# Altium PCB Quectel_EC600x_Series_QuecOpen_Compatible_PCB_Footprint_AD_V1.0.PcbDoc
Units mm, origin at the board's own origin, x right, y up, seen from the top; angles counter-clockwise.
Board outline 152.4 x 101.6 mm, 2 copper layers (Top Layer, Bottom Layer); 1 components, 0 nets, 148 pads, 0 vias.
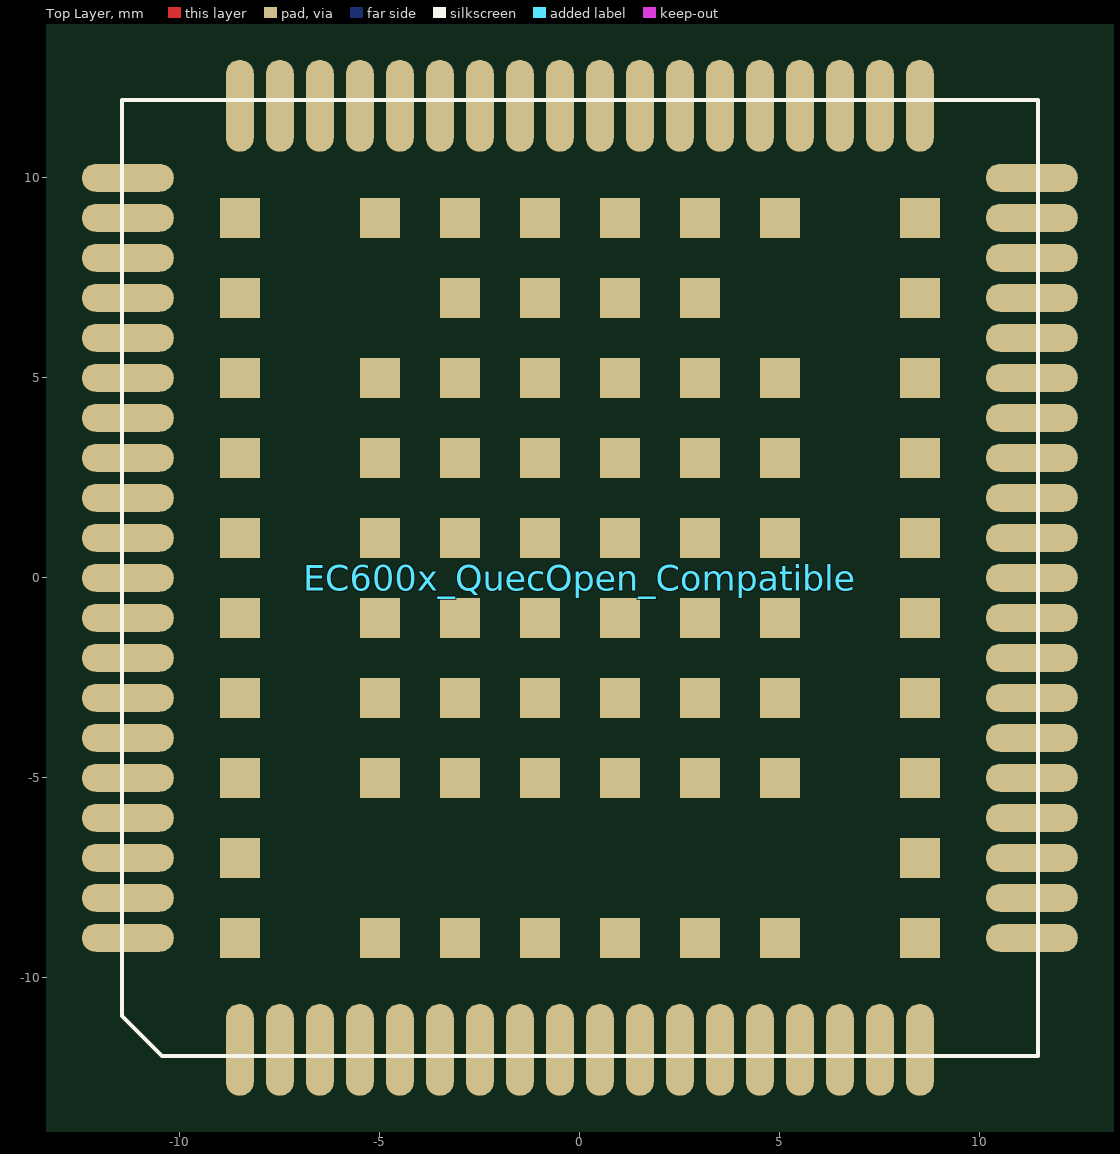
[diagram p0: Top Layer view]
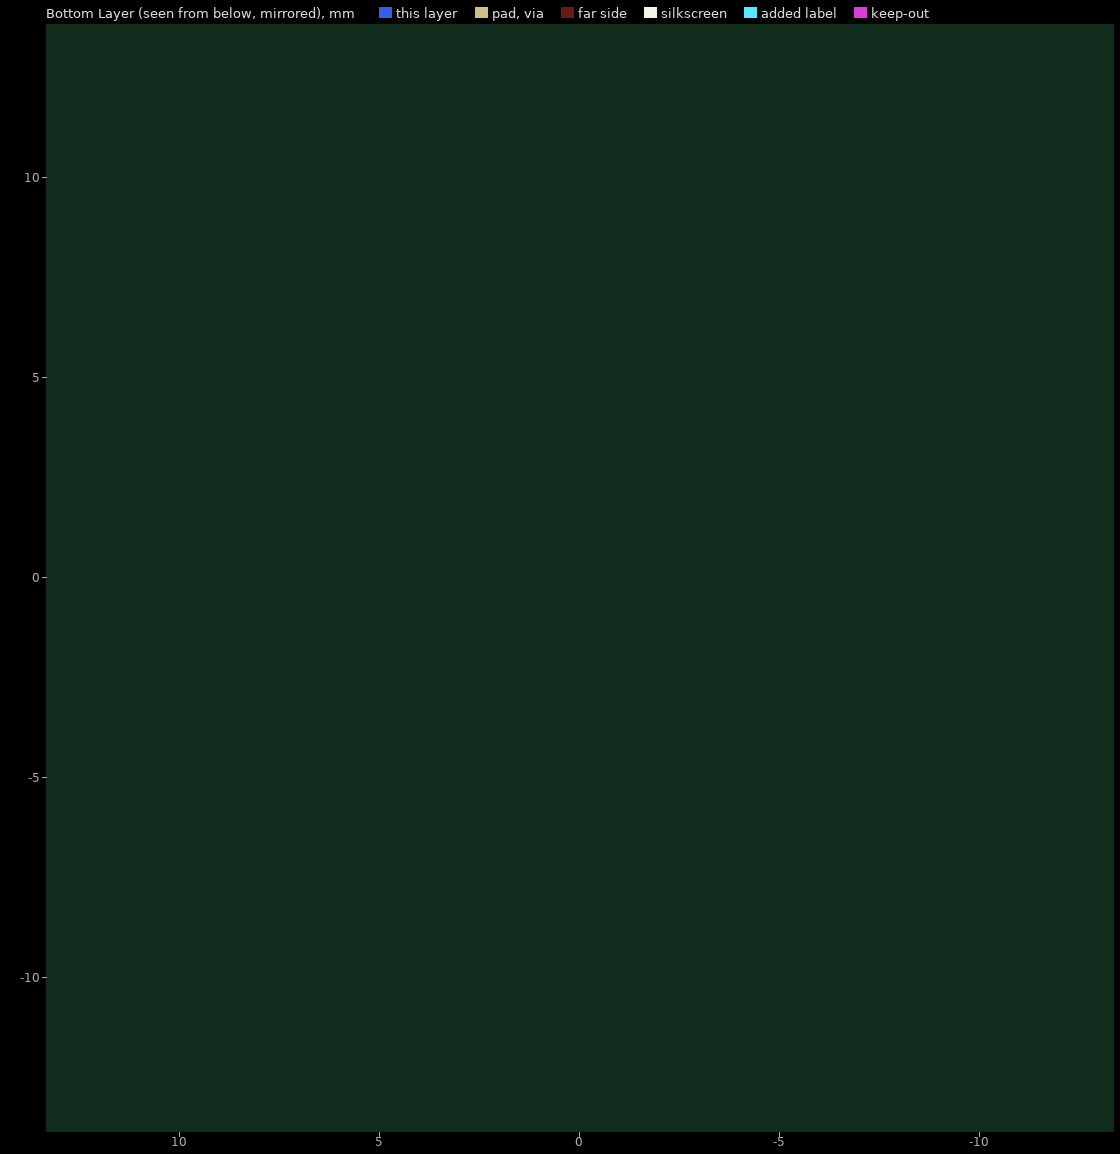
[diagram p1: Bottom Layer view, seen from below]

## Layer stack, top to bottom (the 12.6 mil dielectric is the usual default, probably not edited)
Top Solder: solder mask 0.0102, Solder Resist, Dk 3.5
Top Layer: signal copper 0.0356
Dielectric1: dielectric 0.32, FR-4, Dk 4.8
Bottom Layer: signal copper 0.0356
Bottom Solder: solder mask 0.0102, Solder Resist, Dk 3.5

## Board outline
-80.899,-52.07 71.501,-52.07 71.501,49.53 -80.899,49.53

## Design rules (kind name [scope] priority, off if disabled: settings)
Clearance [All] p1: gap=0.254
PolygonConnect [All] p1: connectstyle=Relief reliefconductorwidth=0.254 reliefentries=4 polygonreliefangle="90 Angle" airgapwidth=0.254
RoutingVias [All] p1: holewidth=0.711 width=1.27 viastyle="Through Hole" minholewidth=0.711 minwidth=1.27 maxholewidth=0.711 maxwidth=1.27
SolderMaskExpansion [All] p1: expansion=0.102
Width [All] p1: maxlimit=0.254 minlimit=0.254 preferedwidth=0.254
30 further rules are at their usual default settings.

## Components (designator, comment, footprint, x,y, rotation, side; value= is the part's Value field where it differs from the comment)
EC600x_QuecOpen_Compatible "Comment" EC600x_QuecOpen_Compatible 0,0 r0 top

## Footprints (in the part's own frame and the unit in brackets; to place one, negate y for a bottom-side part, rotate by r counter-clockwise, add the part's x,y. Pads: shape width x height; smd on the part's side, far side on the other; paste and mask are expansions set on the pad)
EC600x_QuecOpen_Compatible [mm] "EC600x_QuecOpen_Compatible Module LCC76PIN LGA72PIN H2.4mm RO"
  oval 0.7x2.3 smd mask+0.05: 1(-8.5,-11.8) 2(-7.5,-11.8) 3(-6.5,-11.8) 4(-5.5,-11.8) 5(-4.5,-11.8) 6(-3.5,-11.8) 7(-2.5,-11.8) 8(-1.5,-11.8) 9(-0.5,-11.8) 10(0.5,-11.8) 11(1.5,-11.8) 12(2.5,-11.8) 13(3.5,-11.8) 14(4.5,-11.8) 15(5.5,-11.8) 16(6.5,-11.8) 17(7.5,-11.8) 18(8.5,-11.8) 39(8.5,11.8) 40(7.5,11.8) 41(6.5,11.8) 42(5.5,11.8) 43(4.5,11.8) 44(3.5,11.8) 45(2.5,11.8) 46(1.5,11.8) 47(0.5,11.8) 48(-0.5,11.8) 49(-1.5,11.8) 50(-2.5,11.8) 51(-3.5,11.8) 52(-4.5,11.8) 53(-5.5,11.8) 54(-6.5,11.8) 55(-7.5,11.8) 56(-8.5,11.8)
  oval 2.3x0.7 smd mask+0.05: 19(11.3,-9) 20(11.3,-8) 21(11.3,-7) 22(11.3,-6) 23(11.3,-5) 24(11.3,-4) 25(11.3,-3) 26(11.3,-2) 27(11.3,-1) 28(11.3,0) 29(11.3,1) 30(11.3,2) 31(11.3,3) 32(11.3,4) 33(11.3,5) 34(11.3,6) 35(11.3,7) 36(11.3,8) 37(11.3,9) 38(11.3,10) 57(-11.3,10) 58(-11.3,9) 59(-11.3,8) 60(-11.3,7) 61(-11.3,6) 62(-11.3,5) 63(-11.3,4) 64(-11.3,3) 65(-11.3,2) 66(-11.3,1) 67(-11.3,0) 68(-11.3,-1) 69(-11.3,-2) 70(-11.3,-3) 71(-11.3,-4) 72(-11.3,-5) 73(-11.3,-6) 74(-11.3,-7) 75(-11.3,-8) 76(-11.3,-9)
  rect 1x1 smd mask+0.05: 77(-3,-3) 78(-1,-3) 79(1,-3) 80(3,-3) 81(3,-1) 82(3,1) 83(3,3) 84(1,3) 85(-1,3) 86(-3,3) 87(-3,1) 88(-3,-1) 89(-1,-1) 90(1,-1) 91(1,1) 92(-1,1) 93(-5,-5) 94(-3,-5) 95(-1,-5) 96(1,-5) 97(3,-5) 98(5,-5) 99(5,-3) 100(5,-1) 101(5,1) 102(5,3) 103(5,5) 104(3,5) 105(1,5) 106(-1,5) 107(-3,5) 108(-5,5) 109(-5,3) 110(-5,1) 111(-5,-1) 112(-5,-3) 113(-8.5,-9) 114(-5,-9) 115(-3,-9) 116(-1,-9) 117(1,-9) 118(3,-9) 119(5,-9) 120(8.5,-9) 121(8.5,-7) 122(8.5,-5) 123(8.5,-3) 124(8.5,-1) 125(8.5,1) 126(8.5,3) 127(8.5,5) 128(8.5,7) 129(8.5,9) 130(5,9) 131(3,9) 132(1,9) 133(-1,9) 134(-3,9) 135(-5,9) 136(-8.5,9) 137(-8.5,7) 138(-8.5,5) 139(-8.5,3) 140(-8.5,1) 141(-8.5,-1) 142(-8.5,-3) 143(-8.5,-5) 144(-8.5,-7) 145(3,7) 146(1,7) 147(-1,7) 148(-3,7)
  silkscreen extent -11.45,-11.95 11.45,11.95

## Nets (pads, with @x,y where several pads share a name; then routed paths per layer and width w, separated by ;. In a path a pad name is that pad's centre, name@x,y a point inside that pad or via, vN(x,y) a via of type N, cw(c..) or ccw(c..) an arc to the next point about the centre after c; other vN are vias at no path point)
pads on no net: EC600x_QuecOpen_Compatible.1 EC600x_QuecOpen_Compatible.2 EC600x_QuecOpen_Compatible.3 EC600x_QuecOpen_Compatible.4 EC600x_QuecOpen_Compatible.5 EC600x_QuecOpen_Compatible.6 EC600x_QuecOpen_Compatible.7 EC600x_QuecOpen_Compatible.8 EC600x_QuecOpen_Compatible.9 EC600x_QuecOpen_Compatible.10 EC600x_QuecOpen_Compatible.11 EC600x_QuecOpen_Compatible.12 EC600x_QuecOpen_Compatible.13 EC600x_QuecOpen_Compatible.14 EC600x_QuecOpen_Compatible.15 EC600x_QuecOpen_Compatible.16 EC600x_QuecOpen_Compatible.17 EC600x_QuecOpen_Compatible.18 EC600x_QuecOpen_Compatible.19 EC600x_QuecOpen_Compatible.20 EC600x_QuecOpen_Compatible.21 EC600x_QuecOpen_Compatible.22 EC600x_QuecOpen_Compatible.23 EC600x_QuecOpen_Compatible.24 EC600x_QuecOpen_Compatible.25 EC600x_QuecOpen_Compatible.26 EC600x_QuecOpen_Compatible.27 EC600x_QuecOpen_Compatible.28 EC600x_QuecOpen_Compatible.29 EC600x_QuecOpen_Compatible.30 EC600x_QuecOpen_Compatible.31 EC600x_QuecOpen_Compatible.32 EC600x_QuecOpen_Compatible.33 EC600x_QuecOpen_Compatible.34 EC600x_QuecOpen_Compatible.35 EC600x_QuecOpen_Compatible.36 EC600x_QuecOpen_Compatible.37 EC600x_QuecOpen_Compatible.38 EC600x_QuecOpen_Compatible.39 EC600x_QuecOpen_Compatible.40 EC600x_QuecOpen_Compatible.41 EC600x_QuecOpen_Compatible.42 EC600x_QuecOpen_Compatible.43 EC600x_QuecOpen_Compatible.44 EC600x_QuecOpen_Compatible.45 EC600x_QuecOpen_Compatible.46 EC600x_QuecOpen_Compatible.47 EC600x_QuecOpen_Compatible.48 EC600x_QuecOpen_Compatible.49 EC600x_QuecOpen_Compatible.50 EC600x_QuecOpen_Compatible.51 EC600x_QuecOpen_Compatible.52 EC600x_QuecOpen_Compatible.53 EC600x_QuecOpen_Compatible.54 EC600x_QuecOpen_Compatible.55 EC600x_QuecOpen_Compatible.56 EC600x_QuecOpen_Compatible.57 EC600x_QuecOpen_Compatible.58 EC600x_QuecOpen_Compatible.59 EC600x_QuecOpen_Compatible.60 EC600x_QuecOpen_Compatible.61 EC600x_QuecOpen_Compatible.62 EC600x_QuecOpen_Compatible.63 EC600x_QuecOpen_Compatible.64 EC600x_QuecOpen_Compatible.65 EC600x_QuecOpen_Compatible.66 EC600x_QuecOpen_Compatible.67 EC600x_QuecOpen_Compatible.68 EC600x_QuecOpen_Compatible.69 EC600x_QuecOpen_Compatible.70 EC600x_QuecOpen_Compatible.71 EC600x_QuecOpen_Compatible.72 EC600x_QuecOpen_Compatible.73 EC600x_QuecOpen_Compatible.74 EC600x_QuecOpen_Compatible.75 EC600x_QuecOpen_Compatible.76 EC600x_QuecOpen_Compatible.77 EC600x_QuecOpen_Compatible.78 EC600x_QuecOpen_Compatible.79 EC600x_QuecOpen_Compatible.80 EC600x_QuecOpen_Compatible.81 EC600x_QuecOpen_Compatible.82 EC600x_QuecOpen_Compatible.83 EC600x_QuecOpen_Compatible.84 EC600x_QuecOpen_Compatible.85 EC600x_QuecOpen_Compatible.86 EC600x_QuecOpen_Compatible.87 EC600x_QuecOpen_Compatible.88 EC600x_QuecOpen_Compatible.89 EC600x_QuecOpen_Compatible.90 EC600x_QuecOpen_Compatible.91 EC600x_QuecOpen_Compatible.92 EC600x_QuecOpen_Compatible.93 EC600x_QuecOpen_Compatible.94 EC600x_QuecOpen_Compatible.95 EC600x_QuecOpen_Compatible.96 EC600x_QuecOpen_Compatible.97 EC600x_QuecOpen_Compatible.98 EC600x_QuecOpen_Compatible.99 EC600x_QuecOpen_Compatible.100 EC600x_QuecOpen_Compatible.101 EC600x_QuecOpen_Compatible.102 EC600x_QuecOpen_Compatible.103 EC600x_QuecOpen_Compatible.104 EC600x_QuecOpen_Compatible.105 EC600x_QuecOpen_Compatible.106 EC600x_QuecOpen_Compatible.107 EC600x_QuecOpen_Compatible.108 EC600x_QuecOpen_Compatible.109 EC600x_QuecOpen_Compatible.110 EC600x_QuecOpen_Compatible.111 EC600x_QuecOpen_Compatible.112 EC600x_QuecOpen_Compatible.113 EC600x_QuecOpen_Compatible.114 EC600x_QuecOpen_Compatible.115 EC600x_QuecOpen_Compatible.116 EC600x_QuecOpen_Compatible.117 EC600x_QuecOpen_Compatible.118 EC600x_QuecOpen_Compatible.119 EC600x_QuecOpen_Compatible.120 EC600x_QuecOpen_Compatible.121 EC600x_QuecOpen_Compatible.122 EC600x_QuecOpen_Compatible.123 EC600x_QuecOpen_Compatible.124 EC600x_QuecOpen_Compatible.125 EC600x_QuecOpen_Compatible.126 EC600x_QuecOpen_Compatible.127 EC600x_QuecOpen_Compatible.128 EC600x_QuecOpen_Compatible.129 EC600x_QuecOpen_Compatible.130 EC600x_QuecOpen_Compatible.131 EC600x_QuecOpen_Compatible.132 EC600x_QuecOpen_Compatible.133 EC600x_QuecOpen_Compatible.134 EC600x_QuecOpen_Compatible.135 EC600x_QuecOpen_Compatible.136 EC600x_QuecOpen_Compatible.137 EC600x_QuecOpen_Compatible.138 EC600x_QuecOpen_Compatible.139 EC600x_QuecOpen_Compatible.140 EC600x_QuecOpen_Compatible.141 EC600x_QuecOpen_Compatible.142 EC600x_QuecOpen_Compatible.143 EC600x_QuecOpen_Compatible.144 EC600x_QuecOpen_Compatible.145 EC600x_QuecOpen_Compatible.146 EC600x_QuecOpen_Compatible.147 EC600x_QuecOpen_Compatible.148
